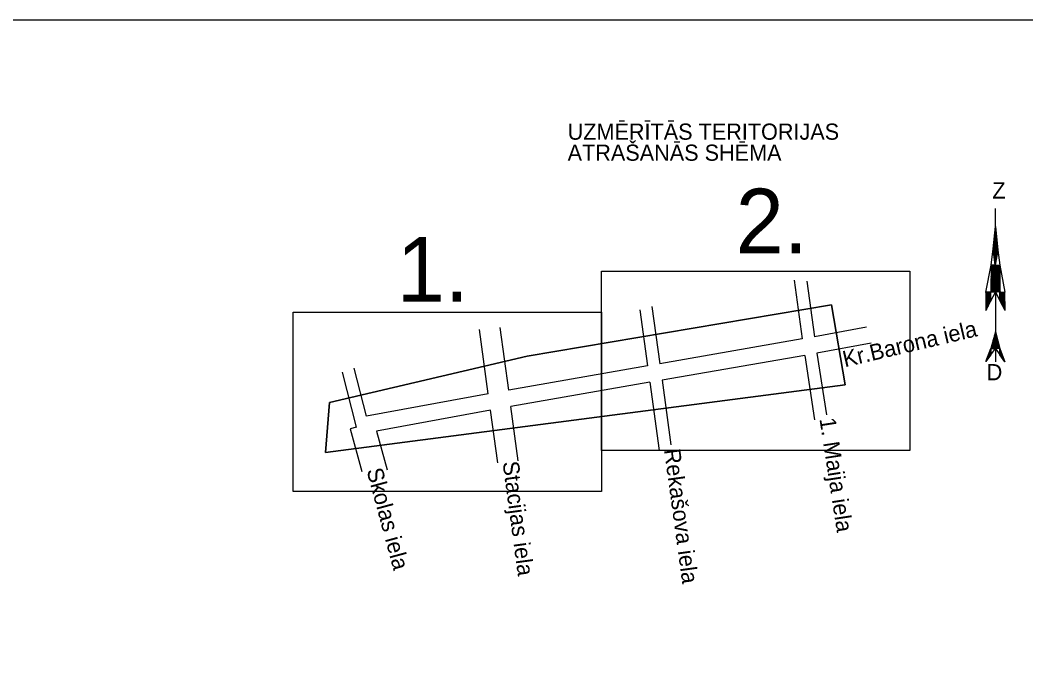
# Model space of a CAD drawing. Extents: x 728492 to 729038, y 272968 to 273171.
# Drawn here: x 728700.1 to 728762.3, y 273111.8 to 273152.3 of the extents above; entities that cross this region are included whole.
import ezdxf

# ---------------------------------------------------------------- set-up
doc = ezdxf.new("R2010")
doc.units = 0
doc.layers.add('RAMI_PLAN_####_TKST_#', color=7, linetype='Continuous')

msp = doc.modelspace()

# ---------------------------------------------------------------- linework, layer by layer
at = {"layer": 'RAMI_PLAN_####_TKST_#'}
for p, q in [((728760.445, 273139.532), (728760.445, 273140.642)), ((728760.293, 273138.146), (728760.445, 273139.532)), ((728760.385, 273138.991), (728760.514, 273138.862)), ((728760.39, 273139.031), (728760.509, 273138.913)), ((728760.394, 273139.072), (728760.504, 273138.962)), ((728760.399, 273139.112), (728760.499, 273139.012)), ((728760.403, 273139.152), (728760.493, 273139.063)), ((728760.408, 273139.193), (728760.488, 273139.112)), ((728760.412, 273139.233), (728760.483, 273139.161)), ((728760.416, 273139.273), (728760.478, 273139.212)), ((728760.421, 273139.314), (728760.473, 273139.262)), ((728760.425, 273139.354), (728760.467, 273139.312)), ((728760.43, 273139.394), (728760.462, 273139.363)), ((728760.434, 273139.434), (728760.457, 273139.411)), ((728760.439, 273139.475), (728760.452, 273139.462)), ((728760.445, 273139.532), (728760.597, 273138.062)), ((728760.319, 273138.385), (728760.592, 273138.112)), ((728760.323, 273138.425), (728760.586, 273138.163)), ((728760.328, 273138.465), (728760.581, 273138.212)), ((728760.332, 273138.506), (728760.576, 273138.263)), ((728760.337, 273138.546), (728760.571, 273138.313)), ((728760.341, 273138.586), (728760.566, 273138.362)), ((728760.346, 273138.628), (728760.56, 273138.413)), ((728760.35, 273138.667), (728760.555, 273138.462)), ((728760.354, 273138.707), (728760.55, 273138.511)), ((728760.359, 273138.749), (728760.545, 273138.562)), ((728760.363, 273138.788), (728760.54, 273138.612)), ((728760.368, 273138.828), (728760.535, 273138.663)), ((728760.372, 273138.87), (728760.53, 273138.712)), ((728760.377, 273138.91), (728760.524, 273138.762)), ((728760.381, 273138.951), (728760.519, 273138.812)), ((728760.171, 273137.137), (728760.293, 273138.146)), ((728760.433, 273137.137), (728760.293, 273138.146)), ((728760.293, 273138.142), (728760.563, 273137.871)), ((728760.297, 273138.184), (728760.57, 273137.909)), ((728760.3, 273138.09), (728760.556, 273137.833)), ((728760.301, 273138.224), (728760.577, 273137.949)), ((728760.306, 273138.265), (728760.584, 273137.987)), ((728760.308, 273138.039), (728760.55, 273137.795)), ((728760.31, 273138.305), (728760.59, 273138.025)), ((728760.315, 273138.345), (728760.597, 273138.063)), ((728760.315, 273137.985), (728760.543, 273137.757)), ((728760.322, 273137.934), (728760.536, 273137.719)), ((728760.33, 273137.881), (728760.53, 273137.681)), ((728760.337, 273137.83), (728760.523, 273137.643)), ((728760.344, 273137.778), (728760.516, 273137.605)), ((728760.597, 273138.062), (728760.433, 273137.137)), ((728760.597, 273138.062), (728760.714, 273137.137)), ((728759.838, 273135.466), (728760.171, 273137.137)), ((728760.171, 273137.137), (728760.16, 273135.491)), ((728760.169, 273136.893), (728760.413, 273137.137)), ((728760.17, 273137.027), (728760.278, 273137.137)), ((728760.17, 273136.983), (728760.324, 273137.137)), ((728760.17, 273136.938), (728760.369, 273137.137)), ((728760.171, 273137.118), (728760.189, 273137.137)), ((728760.171, 273137.074), (728760.235, 273137.137)), ((728760.433, 273137.137), (728760.171, 273137.137)), ((728760.351, 273137.725), (728760.509, 273137.567)), ((728760.359, 273137.673), (728760.503, 273137.53)), ((728760.366, 273137.621), (728760.496, 273137.491)), ((728760.373, 273137.57), (728760.489, 273137.453)), ((728760.38, 273137.517), (728760.483, 273137.416)), ((728760.387, 273137.466), (728760.476, 273137.377)), ((728760.395, 273137.413), (728760.469, 273137.34)), ((728760.402, 273137.361), (728760.462, 273137.301)), ((728760.409, 273137.309), (728760.456, 273137.263)), ((728760.416, 273137.257), (728760.449, 273137.225)), ((728760.424, 273137.205), (728760.442, 273137.187)), ((728760.433, 273137.137), (728760.714, 273137.137)), ((728760.443, 273135.481), (728760.433, 273137.137)), ((728760.433, 273137.121), (728760.714, 273136.841)), ((728760.463, 273137.137), (728760.714, 273136.885)), ((728760.508, 273137.137), (728760.714, 273136.93)), ((728760.553, 273137.137), (728760.714, 273136.975)), ((728760.597, 273137.137), (728760.714, 273137.019)), ((728760.642, 273137.137), (728760.714, 273137.064)), ((728760.687, 273137.137), (728760.714, 273137.109)), ((728760.714, 273137.137), (728760.711, 273135.487)), ((728760.714, 273137.137), (728761.017, 273135.481)), ((728760.165, 273136.306), (728760.437, 273136.578)), ((728760.165, 273136.262), (728760.437, 273136.533)), ((728760.166, 273136.442), (728760.436, 273136.711)), ((728760.166, 273136.396), (728760.436, 273136.666)), ((728760.166, 273136.351), (728760.436, 273136.622)), ((728760.167, 273136.577), (728760.435, 273136.845)), ((728760.167, 273136.532), (728760.435, 273136.8)), ((728760.167, 273136.487), (728760.436, 273136.756)), ((728760.168, 273136.712), (728760.434, 273136.978)), ((728760.168, 273136.667), (728760.434, 273136.933)), ((728760.168, 273136.622), (728760.435, 273136.889)), ((728760.169, 273136.848), (728760.433, 273137.111)), ((728760.169, 273136.802), (728760.434, 273137.067)), ((728760.169, 273136.757), (728760.434, 273137.023)), ((728760.434, 273137.077), (728760.714, 273136.796)), ((728760.434, 273137.032), (728760.714, 273136.752)), ((728760.434, 273136.986), (728760.714, 273136.706)), ((728760.434, 273136.941), (728760.714, 273136.662)), ((728760.435, 273136.895), (728760.714, 273136.617)), ((728760.435, 273136.851), (728760.713, 273136.572)), ((728760.435, 273136.806), (728760.713, 273136.528)), ((728760.435, 273136.761), (728760.713, 273136.482)), ((728760.436, 273136.716), (728760.713, 273136.438)), ((728760.436, 273136.67), (728760.713, 273136.393)), ((728760.436, 273136.625), (728760.713, 273136.348)), ((728760.437, 273136.58), (728760.713, 273136.304)), ((728760.437, 273136.536), (728760.713, 273136.259)), ((728760.161, 273135.72), (728760.44, 273135.998)), ((728760.161, 273135.674), (728760.44, 273135.954)), ((728760.161, 273135.628), (728760.441, 273135.909)), ((728760.162, 273135.855), (728760.439, 273136.132)), ((728760.162, 273135.81), (728760.439, 273136.087)), ((728760.162, 273135.765), (728760.44, 273136.042)), ((728760.163, 273136.035), (728760.438, 273136.31)), ((728760.163, 273135.991), (728760.438, 273136.266)), ((728760.163, 273135.945), (728760.439, 273136.22)), ((728760.163, 273135.9), (728760.439, 273136.177)), ((728760.164, 273136.172), (728760.437, 273136.444)), ((728760.164, 273136.125), (728760.438, 273136.4)), ((728760.164, 273136.081), (728760.438, 273136.354)), ((728760.165, 273136.217), (728760.437, 273136.489)), ((728760.437, 273136.49), (728760.713, 273136.215)), ((728760.437, 273136.446), (728760.713, 273136.17)), ((728760.438, 273136.401), (728760.713, 273136.125)), ((728760.438, 273136.355), (728760.713, 273136.08)), ((728760.438, 273136.31), (728760.712, 273136.035)), ((728760.438, 273136.264), (728760.712, 273135.99)), ((728760.439, 273136.22), (728760.712, 273135.946)), ((728760.439, 273136.175), (728760.712, 273135.901)), ((728760.439, 273136.13), (728760.712, 273135.857)), ((728760.439, 273136.085), (728760.712, 273135.812)), ((728760.44, 273136.039), (728760.712, 273135.767)), ((728760.44, 273135.994), (728760.712, 273135.723)), ((728760.44, 273135.949), (728760.712, 273135.678)), ((728760.441, 273135.904), (728760.712, 273135.632)), ((728760.16, 273135.491), (728759.838, 273135.466)), ((728759.838, 273135.466), (728759.854, 273134.349)), ((728759.839, 273135.414), (728759.896, 273135.47)), ((728759.84, 273135.326), (728759.993, 273135.478)), ((728759.84, 273135.369), (728759.944, 273135.474)), ((728759.841, 273135.238), (728760.09, 273135.486)), ((728759.841, 273135.281), (728760.042, 273135.482)), ((728759.842, 273135.193), (728760.138, 273135.49)), ((728759.843, 273135.149), (728760.16, 273135.466)), ((728759.843, 273135.105), (728760.16, 273135.42)), ((728759.844, 273135.061), (728760.16, 273135.376)), ((728759.845, 273135.017), (728760.16, 273135.331)), ((728759.845, 273134.972), (728760.16, 273135.286)), ((728760.16, 273135.584), (728760.441, 273135.864)), ((728760.16, 273135.538), (728760.441, 273135.82)), ((728760.16, 273135.494), (728760.441, 273135.775)), ((728760.16, 273135.491), (728760.443, 273135.481)), ((728760.16, 273134.939), (728760.16, 273135.491)), ((728760.16, 273134.939), (728760.443, 273135.481)), ((728760.201, 273135.49), (728760.442, 273135.731)), ((728760.244, 273135.488), (728760.442, 273135.687)), ((728760.287, 273135.487), (728760.442, 273135.642)), ((728760.33, 273135.485), (728760.442, 273135.597)), ((728760.373, 273135.484), (728760.443, 273135.552)), ((728760.417, 273135.482), (728760.443, 273135.509)), ((728760.443, 273135.481), (728760.435, 273133.024)), ((728760.441, 273135.859), (728760.712, 273135.589)), ((728760.441, 273135.814), (728760.712, 273135.544)), ((728760.441, 273135.769), (728760.711, 273135.5)), ((728760.442, 273135.723), (728760.68, 273135.486)), ((728760.442, 273135.678), (728760.636, 273135.485)), ((728760.442, 273135.633), (728760.592, 273135.484)), ((728760.442, 273135.588), (728760.547, 273135.483)), ((728760.443, 273135.543), (728760.503, 273135.482)), ((728760.443, 273135.498), (728760.461, 273135.481)), ((728760.711, 273135.487), (728760.443, 273135.481)), ((728760.443, 273135.481), (728760.707, 273134.97)), ((728760.707, 273134.97), (728760.711, 273135.487)), ((728760.71, 273135.344), (728761.023, 273135.031)), ((728760.71, 273135.299), (728761.024, 273134.986)), ((728760.71, 273135.255), (728761.024, 273134.941)), ((728760.711, 273135.487), (728761.017, 273135.481)), ((728760.711, 273135.478), (728761.021, 273135.168)), ((728760.711, 273135.433), (728761.022, 273135.122)), ((728760.711, 273135.388), (728761.023, 273135.077)), ((728760.747, 273135.486), (728761.021, 273135.213)), ((728760.793, 273135.485), (728761.02, 273135.259)), ((728760.838, 273135.484), (728761.019, 273135.304)), ((728760.883, 273135.484), (728761.019, 273135.348)), ((728760.93, 273135.483), (728761.018, 273135.395)), ((728760.976, 273135.482), (728761.017, 273135.441)), ((728761.033, 273134.349), (728761.017, 273135.481)), ((728759.846, 273134.928), (728760.16, 273135.241)), ((728759.847, 273134.885), (728760.16, 273135.197)), ((728759.847, 273134.84), (728760.16, 273135.152)), ((728759.848, 273134.796), (728760.16, 273135.107)), ((728759.849, 273134.752), (728760.16, 273135.063)), ((728759.849, 273134.707), (728760.16, 273135.018)), ((728759.85, 273134.663), (728760.16, 273134.973)), ((728759.85, 273134.62), (728760.149, 273134.918)), ((728759.851, 273134.575), (728760.101, 273134.825)), ((728759.852, 273134.531), (728760.053, 273134.732)), ((728759.852, 273134.486), (728760.005, 273134.639)), ((728759.854, 273134.349), (728760.16, 273134.939)), ((728761.033, 273134.349), (728760.707, 273134.97)), ((728760.708, 273135.077), (728761.027, 273134.759)), ((728760.708, 273135.033), (728761.028, 273134.713)), ((728760.708, 273134.988), (728761.028, 273134.668)), ((728760.709, 273135.21), (728761.025, 273134.894)), ((728760.709, 273135.165), (728761.026, 273134.849)), ((728760.709, 273135.122), (728761.026, 273134.803)), ((728760.735, 273134.916), (728761.029, 273134.622)), ((728760.785, 273134.821), (728761.03, 273134.577)), ((728760.835, 273134.726), (728761.03, 273134.532)), ((728760.884, 273134.632), (728761.031, 273134.485)), ((728759.853, 273134.442), (728759.956, 273134.545)), ((728759.854, 273134.399), (728759.909, 273134.454)), ((728760.933, 273134.539), (728761.032, 273134.44)), ((728760.983, 273134.444), (728761.032, 273134.394)), ((728760.435, 273133.024), (728760.16, 273131.999)), ((728760.339, 273132.665), (728760.439, 273132.765)), ((728760.355, 273132.726), (728760.438, 273132.808)), ((728760.371, 273132.786), (728760.438, 273132.853)), ((728760.387, 273132.847), (728760.437, 273132.897)), ((728760.404, 273132.91), (728760.436, 273132.941)), ((728760.421, 273132.97), (728760.436, 273132.986)), ((728760.435, 273133.024), (728760.711, 273131.999)), ((728760.451, 273132.003), (728760.435, 273133.024)), ((728760.436, 273132.949), (728760.462, 273132.923)), ((728760.437, 273132.903), (728760.479, 273132.861)), ((728760.438, 273132.858), (728760.495, 273132.801)), ((728760.438, 273132.811), (728760.512, 273132.738)), ((728760.439, 273132.766), (728760.529, 273132.677)), ((728760.166, 273131.999), (728760.447, 273132.28)), ((728760.174, 273132.052), (728760.446, 273132.324)), ((728760.191, 273132.114), (728760.445, 273132.368)), ((728760.207, 273132.174), (728760.445, 273132.412)), ((728760.212, 273131.999), (728760.447, 273132.236)), ((728760.224, 273132.236), (728760.444, 273132.456)), ((728760.24, 273132.296), (728760.443, 273132.501)), ((728760.256, 273132.358), (728760.443, 273132.544)), ((728760.256, 273132), (728760.448, 273132.191)), ((728760.273, 273132.419), (728760.442, 273132.588)), ((728760.289, 273132.481), (728760.441, 273132.632)), ((728760.302, 273132.001), (728760.449, 273132.148)), ((728760.305, 273132.541), (728760.44, 273132.676)), ((728760.322, 273132.604), (728760.44, 273132.721)), ((728760.44, 273132.721), (728760.545, 273132.616)), ((728760.441, 273132.674), (728760.562, 273132.555)), ((728760.441, 273132.629), (728760.578, 273132.492)), ((728760.442, 273132.584), (728760.595, 273132.432)), ((728760.443, 273132.539), (728760.612, 273132.369)), ((728760.443, 273132.494), (728760.628, 273132.309)), ((728760.444, 273132.447), (728760.644, 273132.247)), ((728760.445, 273132.402), (728760.661, 273132.186)), ((728760.446, 273132.357), (728760.678, 273132.123)), ((728760.446, 273132.312), (728760.694, 273132.064)), ((728760.447, 273132.265), (728760.711, 273132.002)), ((728760.448, 273132.22), (728760.667, 273131.999)), ((728760.448, 273132.174), (728760.624, 273132)), ((728759.842, 273131.19), (728760.16, 273131.999)), ((728760.16, 273131.6), (728759.842, 273131.19)), ((728759.903, 273131.345), (728760.16, 273131.601)), ((728759.931, 273131.418), (728760.16, 273131.646)), ((728759.96, 273131.492), (728760.16, 273131.691)), ((728759.989, 273131.566), (728760.16, 273131.736)), ((728760.019, 273131.64), (728760.16, 273131.781)), ((728760.047, 273131.713), (728760.16, 273131.826)), ((728760.076, 273131.786), (728760.16, 273131.87)), ((728760.106, 273131.862), (728760.16, 273131.915)), ((728760.134, 273131.934), (728760.16, 273131.959)), ((728760.16, 273131.999), (728760.451, 273132.003)), ((728760.16, 273131.6), (728760.451, 273132.003)), ((728760.16, 273131.999), (728760.16, 273131.6)), ((728760.348, 273132.002), (728760.45, 273132.103)), ((728760.394, 273132.002), (728760.45, 273132.059)), ((728760.451, 273132.003), (728760.435, 273131.17)), ((728760.449, 273132.13), (728760.577, 273132.001)), ((728760.45, 273132.084), (728760.531, 273132.002)), ((728760.451, 273132.038), (728760.486, 273132.003)), ((728760.711, 273131.999), (728760.451, 273132.003)), ((728760.451, 273132.003), (728760.711, 273131.606)), ((728760.711, 273131.999), (728761.021, 273131.17)), ((728760.711, 273131.606), (728760.711, 273131.999)), ((728760.711, 273131.941), (728760.746, 273131.906)), ((728760.711, 273131.896), (728760.772, 273131.836)), ((728760.711, 273131.851), (728760.799, 273131.764)), ((728760.711, 273131.806), (728760.826, 273131.692)), ((728760.711, 273131.762), (728760.853, 273131.62)), ((728760.711, 273131.718), (728760.88, 273131.549)), ((728760.711, 273131.673), (728760.906, 273131.479)), ((728760.711, 273131.628), (728760.933, 273131.407)), ((728761.021, 273131.17), (728760.711, 273131.606)), ((728760.768, 273131.526), (728760.96, 273131.335)), ((728759.874, 273131.272), (728760.01, 273131.408)), ((728760.879, 273131.37), (728760.987, 273131.262)), ((728720.927, 273127.137), (728720.543, 273127.037))]:
    msp.add_line(p, q, dxfattribs=at)
for points in [[(728492.227, 273152.288), (728492.227, 272968.263), (728765.305, 272968.263), (728765.305, 273152.288)], [(728736.078, 273136.778), (728755.139, 273136.778), (728755.139, 273125.682), (728736.078, 273125.682)], [(728719.26, 273128.651), (728731.487, 273131.517), (728750.305, 273134.696), (728751.142, 273129.744), (728719.013, 273125.564)], [(728717.016, 273134.247), (728736.078, 273134.247), (728736.078, 273123.152), (728717.016, 273123.152)]]:
    msp.add_lwpolyline(points, close=True, dxfattribs=at)
for points in [[(728747.998, 273136.217), (728748.5, 273132.582)], [(728748.782, 273136.156), (728749.257, 273132.718)], [(728719.013, 273125.564), (728751.142, 273129.744), (728750.305, 273134.696), (728731.487, 273131.517), (728719.26, 273128.651), (728719.013, 273125.564)], [(728738.459, 273134.376), (728738.933, 273130.92)], [(728739.203, 273134.6), (728739.69, 273131.052)], [(728729.085, 273129.202), (728728.546, 273133.175)], [(728730.346, 273129.428), (728729.822, 273133.296)], [(728752.475, 273133.312), (728749.257, 273132.718)], [(728748.5, 273132.582), (728739.69, 273131.052)], [(728752.756, 273132.322), (728749.405, 273131.704)], [(728748.649, 273131.569), (728739.829, 273130.037)], [(728748.649, 273131.569), (728749.26, 273127.595)], [(728749.405, 273131.704), (728749.991, 273127.897)], [(728738.933, 273130.92), (728730.346, 273129.428)], [(728720.927, 273127.137), (728720.07, 273130.526)], [(728721.55, 273127.807), (728720.799, 273130.774)], [(728739.072, 273129.905), (728730.484, 273128.413)], [(728739.072, 273129.905), (728739.649, 273125.694)], [(728739.829, 273130.037), (728740.377, 273126.041)], [(728729.085, 273129.202), (728721.55, 273127.807)], [(728730.939, 273125.055), (728730.484, 273128.413)], [(728729.223, 273128.186), (728722.176, 273126.882)], [(728729.665, 273124.924), (728729.223, 273128.186)], [(728720.543, 273127.037), (728721.258, 273124.391)], [(728722.176, 273126.882), (728722.82, 273124.498)]]:
    msp.add_lwpolyline(points, dxfattribs=at)

# ---------------------------------------------------------------- texts
for s, rotation, p in [('UZMĒRĪTĀS TERITORIJAS ', 359.99995, (728733.987, 273144.896)), ('ATRAŠANĀS SHĒMA', 359.99995, (728733.987, 273143.596)), ('Z', 359.99995, (728760.248, 273141.263)), ('Kr.Barona iela', 13.19345, (728751.128, 273130.83)), ('D', 359.99995, (728759.9, 273130.032)), ('1. Maija iela', 278.75134, (728749.557, 273127.641)), ('Rekašova iela', 277.80715, (728739.946, 273125.735)), ('Stacijas iela', 277.72183, (728729.962, 273124.965)), ('Skolas iela', 285.11086, (728721.548, 273124.469))]:
    msp.add_text(s, height=1, rotation=rotation, dxfattribs=at).set_placement(p)
for s, p in [('2.', (728744.382, 273137.869)), ('1.', (728723.423, 273134.881))]:
    msp.add_text(s, height=4, dxfattribs=at).set_placement(p)

doc.saveas('drawing.dxf')
